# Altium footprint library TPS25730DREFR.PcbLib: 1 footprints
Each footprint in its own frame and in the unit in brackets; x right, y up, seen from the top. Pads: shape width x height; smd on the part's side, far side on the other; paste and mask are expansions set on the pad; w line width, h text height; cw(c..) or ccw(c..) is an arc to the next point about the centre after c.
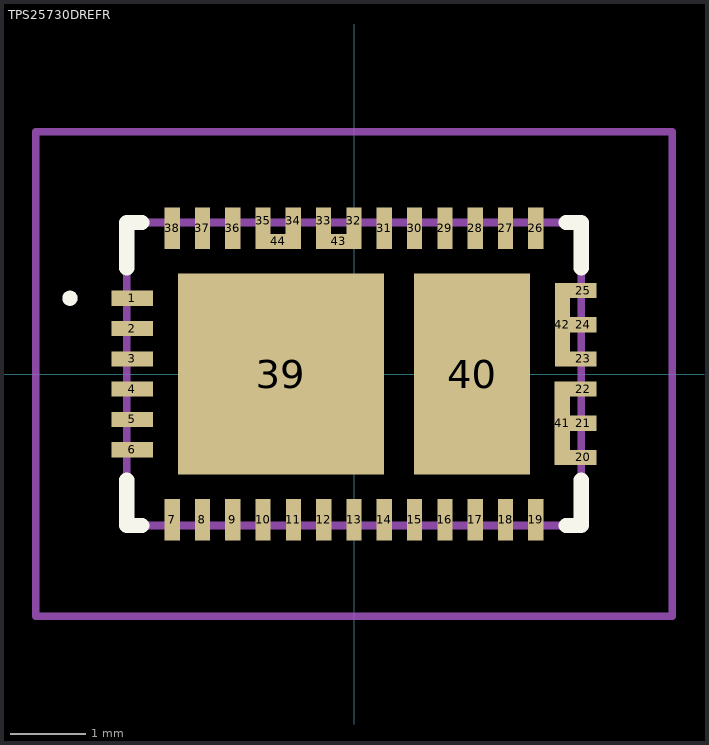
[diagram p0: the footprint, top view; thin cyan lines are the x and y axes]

## TPS25730DREFR [mm]
pads (44):
  rect 0.55x0.2 smd: 1(-2.925,1) 2(-2.925,0.6) 3(-2.925,0.2) 4(-2.925,-0.2) 5(-2.925,-0.6) 6(-2.925,-1)
  rect 0.2x0.55 smd: 7(-2.4,-1.925) 8(-2,-1.925) 9(-1.6,-1.925) 10(-1.2,-1.925) 11(-0.8,-1.925) 12(-0.4,-1.925) 13(0,-1.925) 14(0.4,-1.925) 15(0.8,-1.925) 16(1.2,-1.925) 17(1.6,-1.925) 18(2,-1.925) 19(2.4,-1.925) 26(2.4,1.925) 27(2,1.925) 28(1.6,1.925) 29(1.2,1.925) 30(0.8,1.925) 31(0.4,1.925) 36(-1.6,1.925) 37(-2,1.925) 38(-2.4,1.925)
  rect 0.35x0.2 smd: 20(3.025,-1.1) 21(3.025,-0.65) 22(3.025,-0.2) 23(3.025,0.2) 24(3.025,0.65) 25(3.025,1.1)
  rect 0.2x0.35 smd: 32(-0.001,2.025) 33(-0.401,2.025) 34(-0.801,2.025) 35(-1.201,2.025)
  rect 2.72x2.65 smd: 39(-0.965,0)
  rect 1.53x2.65 smd: 40(1.56,0)
  rect 0.2x1.1 smd: 41(2.749,-0.65) 42(2.75,0.65)
  rect 0.6x0.2 smd: 43(-0.201,1.75) 44(-1.001,1.75)
Top Overlay:
  lines w0.1: -3.8,1 cw(c-3.75,1) -3.7,1 ; -3.8,1 -3.8,1 ; -3.8,1 ccw(c-3.75,1) -3.7,1 ; -3.7,1 -3.7,1
  lines w0.2: -3,-1.4 -3,-2 -2.8,-2 ; -3,1.4 -3,2 -2.8,2 ; 2.8,-2 3,-2 3,-1.4 ; 2.8,2 3,2 3,1.4
Mechanical 15:
  lines w0.1: -3,-2 3,-2 3,2 -3,2 -3,-2
Mechanical 20:
  lines w0.1: -4.2,-3.2 4.2,-3.2 4.2,3.2 -4.2,3.2 -4.2,-3.2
